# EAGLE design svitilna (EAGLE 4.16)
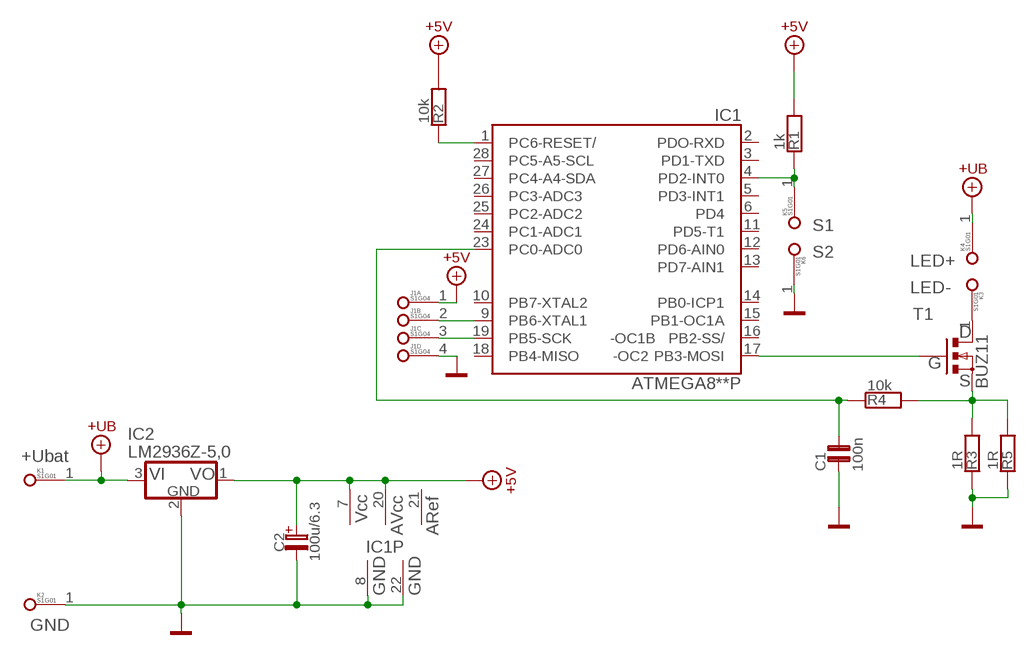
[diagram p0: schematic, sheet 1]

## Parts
C1  100n  C1206  [C1206]
C2  100u/6.3  CTANSMD-D  [CTANSMD-D]
IC1  ATMEGA8**P  ATMEGA8P  [DIL28-3]
IC2  LM2936Z-5,0  LE50ABZ  [TO92]
J1  S1G04  [S1G04]
K1  S1G01  [S1G01]
K2  S1G01  [S1G01]
K3  S1G01  [S1G01]
K4  S1G01  [S1G01]
K5  S1G01  [S1G01]
K6  S1G01  [S1G01]
R1  1k  R1206  [R1206]
R2  10k  R1206  [R1206]
R3  1R  R208-8  [R208-8]
R4  10k  R1206  [R1206]
R5  1R  R0414/15  [R0414/15]
T1  BUZ11  [TO220]

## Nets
+5V: C2.1(+) IC1.7(VCC) IC1.20(AVCC) IC2.1(VO) J1.1 R1.2 R2.2
+UB: IC2.3(VI) K1.1(P) K4.1(P)
GND: C1.1 C2.2(-) IC1.8(GND) IC1.22(GND) IC2.2(GND) J1.4 K2.1(P) K6.1(P) R3.1 R5.1
N$2: IC1.9(PB6-XTAL1) J1.2
N$3: IC1.17(PB3-MOSI) T1.1(G)
N$4: R3.2 R4.2 R5.2 T1.3(S)
N$5: IC1.19(PB5-SCK) J1.3
N$6: C1.2 IC1.23(PC0-ADC0) R4.1
N$8: IC1.1(PC6-RESET/) R2.1
N$10: K3.1(P) T1.2(D)
N$11: IC1.4(PD2-INT0) K5.1(P) R1.1
Unconnected: IC1.2(PDO-RXD) IC1.3(PD1-TXD) IC1.5(PD3-INT1) IC1.6(PD4) IC1.10(PB7-XTAL2) IC1.11(PD5-T1) IC1.12(PD6-AIN0) IC1.13(PD7-AIN1) IC1.14(PB0-ICP1) IC1.15(PB1-OC1A) IC1.16(PB2-SS/) IC1.18(PB4-MISO) IC1.21(AREF) IC1.24(PC1-ADC1) IC1.25(PC2-ADC2) IC1.26(PC3-ADC3) IC1.27(PC4-A4-SDA) IC1.28(PC5-A5-SCL)

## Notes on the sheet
- S1
- S2
- LED+
- LED-
- +Ubat
- GND

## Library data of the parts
C1 = PASSIVE:C
C2 = PASSIVE:CTANSMD
IC1 = io:ATMEGA8**P
IC2 = io:LE50ABZ
J1 = cons:S1G04
K1-K6 = cons:S1G01
R1 R2 R4 R5 = PASSIVE:R
R3 = PASSIVE:R208-8
T1 = active:BUZ11

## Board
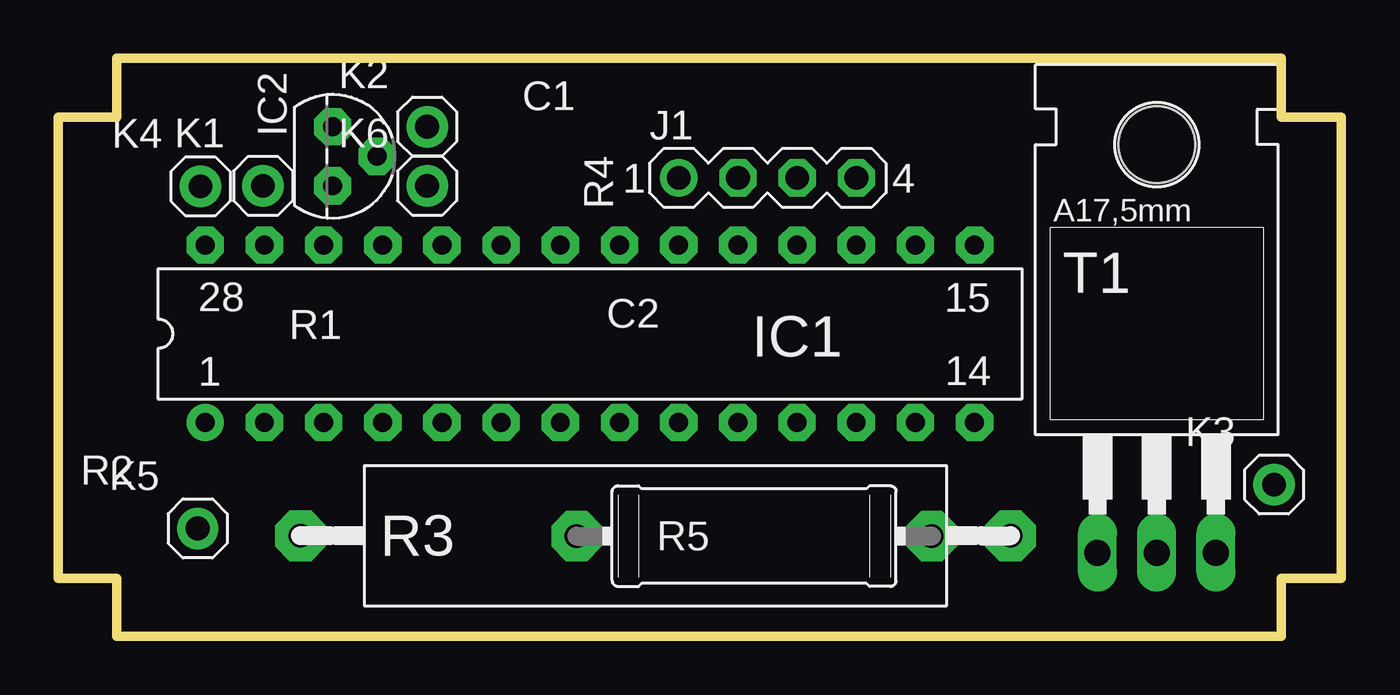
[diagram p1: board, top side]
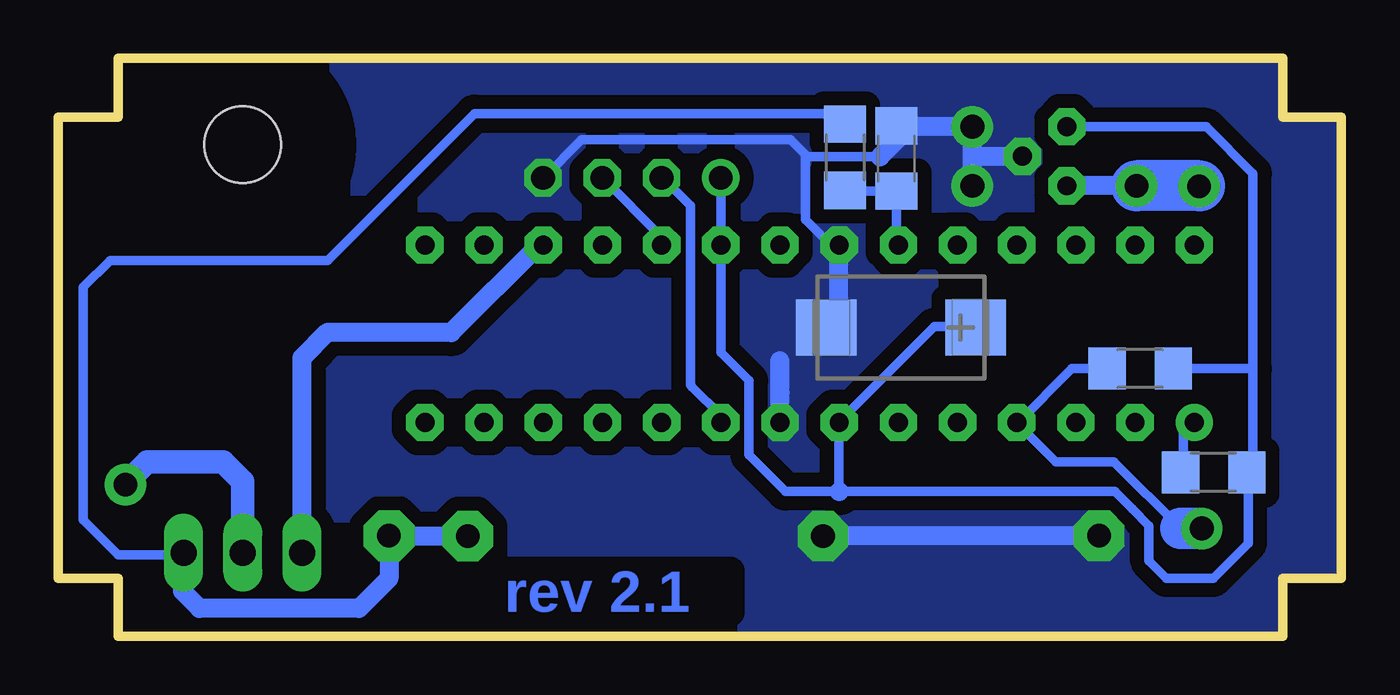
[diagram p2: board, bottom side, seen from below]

Size 55.07 x 24.83 mm. Coordinates in mm from the lower left corner, seen from the top.
Outline: 2.5,0 52.5,0 52.5,2.5 55.07,2.5 55.07,22.3 52.5,22.3 52.5,24.83 2.5,24.83 2.5,22.3 0,22.3 0,2.5 2.5,2.5 2.5,0
Copper layers 16: Bottom 0.035mm
Design rules "default": minimum track width 10mil, minimum drill 24mil, track to track 8mil, track to pad 8mil, pad to pad 8mil, via to via 8mil, smd to smd 8mil, copper to edge 0mil, drill to drill 8mil, minimum pad ring 10mil, minimum via ring 8mil, stop-mask expansion 4mil, vias tented up to drill 0mil, thermal gap 10mil

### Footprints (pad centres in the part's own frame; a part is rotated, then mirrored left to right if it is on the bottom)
C1206 = smd 1.6 x 1.8: 1 -1.4,0; 2 1.4,0
CTANSMD-D = smd 2.6 x 2.4: 1 -3.2,0; 2 3.2,0
DIL28-3 = drill 0.813 pad 1.6 round: 1 -16.51,-3.81 | drill 0.813 pad 1.6 octagon: 2 -13.97,-3.81; 3 -11.43,-3.81; 4 -8.89,-3.81; 5 -6.35,-3.81; 6 -3.81,-3.81; 7 -1.27,-3.81; 8 1.27,-3.81; 9 3.81,-3.81; 10 6.35,-3.81; 11 8.89,-3.81; 12 11.43,-3.81; 13 13.97,-3.81; 14 16.51,-3.81; 15 16.51,3.81; 16 13.97,3.81; 17 11.43,3.81; 18 8.89,3.81; 19 6.35,3.81; 20 3.81,3.81; 21 1.27,3.81; 22 -1.27,3.81; 23 -3.81,3.81; 24 -6.35,3.81; 25 -8.89,3.81; 26 -11.43,3.81; 27 -13.97,3.81; 28 -16.51,3.81
TO92 = drill 0.813 pad 1.6 octagon: 1 -1.27,0; 2 0,1.905; 3 1.27,0
S1G04 = drill 1.016 pad 1.6 round: 1 -3.81,0 | drill 1.016 pad 1.6 octagon: 2 -1.27,0; 3 1.27,0; 4 3.81,0
S1G01 = drill 1.016 pad 1.778 round: 1 0,0
R1206 = smd 1.6 x 1.803: 1 -1.422,0; 2 1.422,0
R208-8 = drill 1.016 pad 2.184 octagon: 1 -15.24,0; 2 15.24,0
R0414/15 = drill 1.016 pad 2.159 octagon: 1 -7.62,0; 2 7.62,0
TO220 = drill 1.118 pad 1.626 long: 1 -2.54,-6.35; 2 0,-6.35; 3 2.54,-6.35 | hole 3.302: 0,11.176

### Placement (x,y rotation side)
C1  19.1,20.52 270 bottom
C2  18.9,13.27 180 bottom
IC1  22.82,13 0 top
IC2  11.78,20.62 270 top
J1  30.45,19.69 0 top
K1  8.79,19.35 0 top
K2  15.84,21.89 0 top
K3  52.18,6.53 0 top
K4  6.1,19.33 0 top
K5  5.99,4.64 0 top
K6  15.84,19.35 0 top
R1  8.63,11.5 0 bottom
R2  5.48,7.05 0 bottom
R3  25.64,4.33 0 top
R4  21.3,20.58 90 bottom
R5  29.87,4.31 0 top
T1  47.15,9.95 0 top

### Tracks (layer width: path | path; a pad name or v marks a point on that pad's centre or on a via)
+5V
  Bottom 0.406: IC2.1 5.8,21.89 3.79,19.88 3.79,11.5 | J1.1 IC1.20 26.63,12.2 25.42,10.99 25.42,7.79 23.86,6.23 21.54,6.23 9.72,6.23 8.97,5.47 8.25,4.75 8.25,3.25 7.5,2.5 5.5,2.5 4,4 4,7 | 21.55,6.23 IC1.7 | 4,7 3.98,7 | 4,7 3.96,7 | 3.79,11.5 3.79,7 4,7 | 3.79,11.5 R1.2 | R2.2 4.25,7.05 4.3,7.1 4,7.1 4,7 | C2.1 15.73,13.3 17.47,13.3 21.55,9.22
  Bottom 0.813: IC1.7 21.54,9.21 21.55,9.22 | 21.54,6.23 21.55,6.23
+UB
  Bottom 0.813: 11.4,19.35 IC2.3 | K1.1 11.4,19.35 | 11.4,19.35 11.42,19.33 | 6.07,19.35 6.08,19.35 K4.1
  Bottom 2.184: 6.08,19.35 K1.1
GND
  Bottom 0.406: IC1.22 21.7,16.66 | 19.8,20.6 23,20.6 | 23,20.6 23,17.9 21.91,16.81 | 34.26,19.65 J1.4 | 34.26,19.65 34.27,19.66 32.6,21.33 23.65,21.33 22.94,20.62 22.96,20.6 23,20.6 | 34.26,19.65 34.26,19.64
  Bottom 0.813: 24.09,10.46 IC1.8 | R3.1 22.76,4.33 | 15.83,20.62 IC2.2 | K6.1 15.84,20.62 15.83,20.62 | 19.8,20.6 18.51,21.89 K2.1 | 24.09,10.46 24.1,10.46 | 21.57,16.79 21.58,16.8 IC1.22 21.91,16.81 21.87,16.77 21.58,16.77 21.58,14.35 | 24.09,10.46 24.1,10.47 24.1,11.83 | K2.1 | K2.1 15.84,20.62 15.83,20.62
  pour Bottom (isolate 0.61, no thermals): 0.25,22 0.25,2.75 2.75,2.75 2.75,0.25 52.25,0.25 52.25,2.75 54.75,2.75 54.75,22 52.25,22 52.25,24.5 2.75,24.5 2.75,22 0.5,22
N$2
  Bottom 0.406: IC1.9 26.63,9.49 27.86,10.72 27.94,10.8 27.94,18.04 27.94,18.5 29.18,19.74
  Bottom 0.813: 29.2,19.76 29.18,19.74 J1.2
N$3
  Bottom 0.813: T1.1 44.61,11.96 43.5,13.07 38.21,13.07 38.21,13.06 38.2,13.05 34.44,16.81 IC1.17
N$4
  Bottom 0.406: 21.34,22.43 21.3,22.39 | 21.34,22.43 21.7,22.43 21.54,22.27 21.55,22.26 21.55,22.19 21.4,22.04 21.39,22.04 21.35,22 R4.2 | 21.34,22.43 21.36,22.45 37.21,22.45 43.51,16.15 52.85,16.15 54,15 54,5 52.5,3.5 49.75,3.5 49.69,3.56 T1.3
  Bottom 0.813: 49.65,3.6 49.55,3.69 | 49.65,3.6 T1.3 | 49.65,3.6 49.73,3.51 49.73,1.94 49,1.21 42.16,1.21 40.88,2.5 R3.2 40.9,4.33 40.9,4.31 | R5.2 40.9,4.31 | 40.9,4.31 40.9,4.3
N$5
  Bottom 0.406: J1.3 29.17,17.16 IC1.19
N$6
  Bottom 0.406: 19.01,16.76 19,16.75 | IC1.23 19.01,16.76 | 19.01,16.76 19.1,16.85 C1.2 21.22,19.12 21.26,19.16 R4.1
N$8
  Bottom 0.406: R2.1 6.85,7.1 | R2.1 | IC1.1 6.78,8.72 6.78,7.02 6.73,7.02 6.7,7.05 R2.1
N$10
  Bottom 1.016: T1.2 47.15,6.65 48,7.5 51.25,7.5 52.23,6.53 | 52.23,6.53 52.25,6.5 | 52.23,6.53 K3.1
N$11
  Bottom 0.406: 13.91,9.15 11.56,11.5 R1.1 10,11.5 | 6.89,4.64 9.75,7.5 12.25,7.5 IC1.4 | IC1.4 14,9.25 | IC1.4
  Bottom 0.813: 13.91,9.15 13.93,9.17 IC1.4
  Bottom 1.778: K5.1 6.89,4.64

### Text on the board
Bottom: rev 2.1
Document: S2 | GND | Ubat | LED+ | LED- | S1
